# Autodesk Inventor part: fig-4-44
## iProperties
Created: 2004-05
Part Number: fig-4-44
Document SubType Name: Modeling
Designer: CADCIM Technologies
Manufacturer: Standard
Standards Organization: Custom
Density: 1 g/cm^3
Author: CADCIM Technologies
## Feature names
1. Revolution1
2. Revolution2
3. Revolution4
